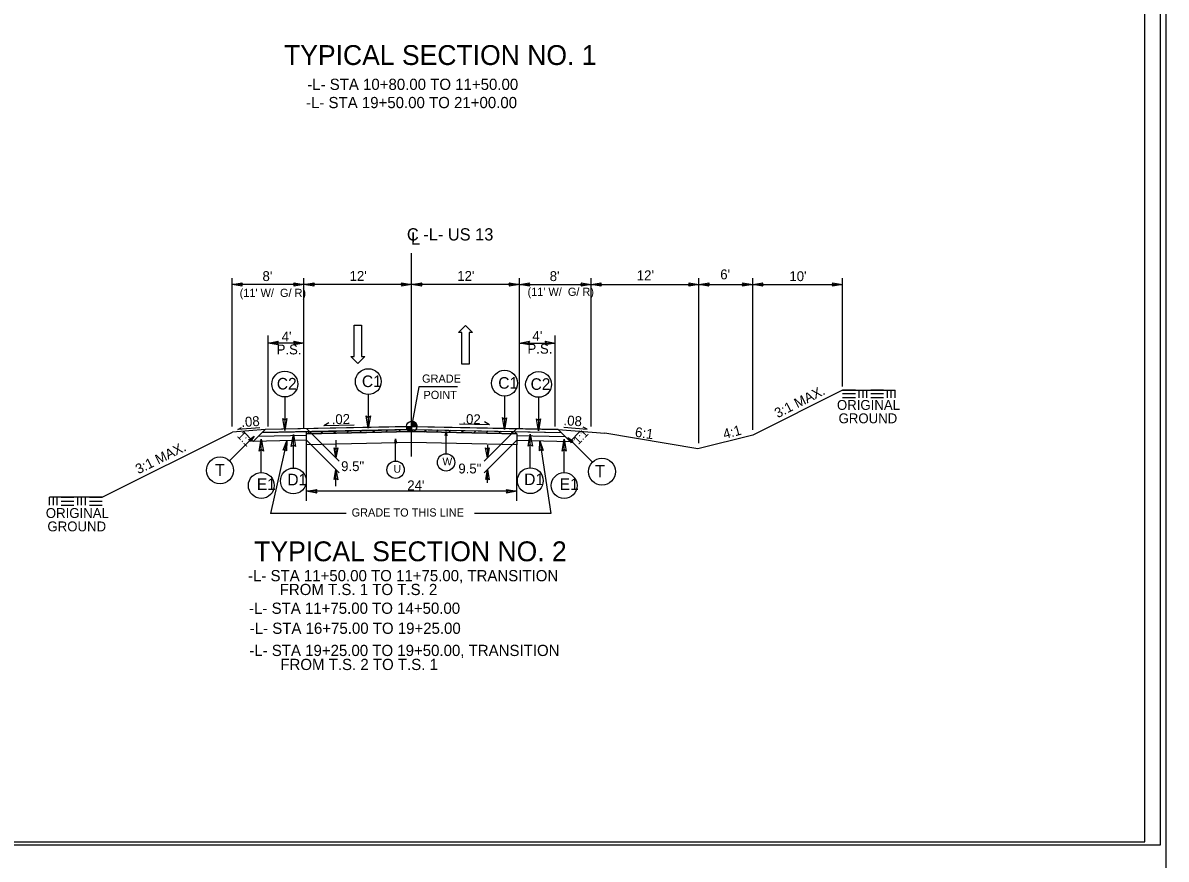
# Model space of a CAD drawing. Extents: x 9470 to 10081, y 10104 to 10463.
# Drawn here: x 9925.2 to 10052.6, y 10259.6 to 10352.7 of the extents above; entities that cross this region are included whole.
import ezdxf

# ---------------------------------------------------------------- set-up
doc = ezdxf.new("R2010")
doc.units = 0
for name, color, linetype in [('Old_Level_1', 7, 'Continuous'), ('Old_Level_11', 7, 'Continuous'), ('Old_Level_2', 7, 'Continuous'), ('Old_Level_21', 7, 'Continuous'), ('Old_Level_32', 7, 'Continuous'), ('Prop Lane Arrow CELL', 7, 'Continuous'), ('Prop Terminator CELL', 7, 'Continuous'), ('Sheet Plot Border Inside CELL', 7, 'Continuous'), ('Sheet Plot Border Outside CELL', 7, 'Continuous'), ('Sheet Typical CELL', 7, 'Continuous'), ('Typical Hinge Slope Arterial CELL', 7, 'Continuous'), ('Typical ID Circle CELL', 7, 'Continuous'), ('Typical Pavement Slope CELL', 7, 'Continuous'), ('Typical Terminator CELL', 7, 'Continuous'), ('Typical Text ID Circle CELL', 7, 'Continuous')]:
    doc.layers.add(name, color=color, linetype=linetype)

msp = doc.modelspace()

# ---------------------------------------------------------------- linework, layer by layer
at = {"layer": 'Old_Level_1'}
for p, q in [((9968.54, 10304.4), (9968.54, 10327.07)), ((9948.54, 10307.74), (9948.54, 10324.27)), ((9956.54, 10323.57), (9948.54, 10323.57)), ((9956.54, 10307.5), (9956.54, 10324.27)), ((9968.54, 10323.57), (9956.54, 10323.57)), ((9980.54, 10323.57), (9968.54, 10323.57)), ((9980.54, 10307.5), (9980.54, 10324.27)), ((9980.54, 10323.57), (9988.54, 10323.57)), ((9988.54, 10307.74), (9988.54, 10324.27)), ((9988.54, 10323.57), (10000.54, 10323.57)), ((10000.54, 10305.9), (10000.54, 10324.27)), ((10000.54, 10323.57), (10006.54, 10323.57)), ((10006.54, 10307.36), (10006.54, 10324.27)), ((10006.54, 10323.57), (10016.54, 10323.57)), ((10016.54, 10312.2), (10016.54, 10324.27)), ((9952.54, 10307.74), (9952.54, 10317.88)), ((9984.54, 10307.74), (9984.54, 10317.88)), ((9956.54, 10317.05), (9952.54, 10317.05)), ((9980.54, 10317.05), (9984.54, 10317.05)), ((10016.54, 10311.8), (10022.4, 10311.8)), ((10017.97, 10311.8), (10016.54, 10311.8)), ((10017.97, 10311.37), (10016.54, 10311.37)), ((10017.97, 10310.94), (10016.54, 10310.94)), ((10018.4, 10310.94), (10018.4, 10311.8)), ((10018.83, 10310.94), (10018.83, 10311.8)), ((10019.25, 10310.94), (10019.25, 10311.8)), ((10021.11, 10311.8), (10019.68, 10311.8)), ((10021.11, 10311.37), (10019.68, 10311.37)), ((10021.11, 10310.94), (10019.68, 10310.94)), ((10021.54, 10310.94), (10021.54, 10311.8)), ((10021.97, 10310.94), (10021.97, 10311.8)), ((10022.4, 10310.94), (10022.4, 10311.8)), ((9968.54, 10307.74), (9968.54, 10308.33)), ((9952.21, 10307.42), (9948.59, 10307.13)), ((9968.54, 10307.74), (9952.21, 10307.42)), ((9956.84, 10307.51), (9960.48, 10303.87)), ((9956.84, 10306.93), (9968.54, 10307.19)), ((9956.96, 10306.94), (9957.2, 10307.18)), ((9958.41, 10306.97), (9958.65, 10307.21)), ((9959.85, 10307), (9960.09, 10307.24)), ((9961.3, 10307.03), (9961.54, 10307.27)), ((9962.74, 10307.06), (9962.98, 10307.3)), ((9964.19, 10307.1), (9964.43, 10307.33)), ((9965.64, 10307.13), (9965.87, 10307.36)), ((9967.08, 10307.16), (9967.31, 10307.39)), ((9967.95, 10307.74), (9968.54, 10307.74)), ((9968.53, 10307.19), (9968.75, 10307.41)), ((9969.12, 10307.74), (9968.54, 10307.74)), ((9968.54, 10307.16), (9968.54, 10307.74)), ((9968.54, 10307.74), (9968.54, 10307.16)), ((9968.54, 10307.74), (9984.86, 10307.42)), ((9968.54, 10307.42), (9985.2, 10307.08)), ((9968.54, 10307.19), (9980.24, 10306.93)), ((9969.91, 10307.16), (9970.14, 10307.39)), ((9971.3, 10307.13), (9971.52, 10307.36)), ((9972.68, 10307.1), (9972.91, 10307.33)), ((9974.06, 10307.07), (9974.3, 10307.3)), ((9975.45, 10307.04), (9975.68, 10307.27)), ((9980.24, 10307.51), (9976.6, 10303.87)), ((9976.83, 10307.01), (9977.07, 10307.25)), ((9978.22, 10306.98), (9978.46, 10307.22)), ((9979.6, 10306.95), (9979.84, 10307.19)), ((9980.24, 10306.93), (9979.99, 10307.19)), ((9984.86, 10307.42), (9990.06, 10307)), ((9954.65, 10306.16), (9952.8, 10298.05)), ((9956.84, 10305.7), (9956.84, 10306.93)), ((9956.84, 10306.21), (9960.48, 10302.57)), ((9968.54, 10305.96), (9956.84, 10305.7)), ((9956.84, 10299.46), (9956.84, 10305.7)), ((9960.1, 10306.22), (9960.1, 10304.25)), ((9980.24, 10305.7), (9968.54, 10305.96)), ((9980.24, 10306.21), (9976.6, 10302.57)), ((9976.98, 10305.68), (9976.98, 10304.25)), ((9980.24, 10306.93), (9980.24, 10305.7)), ((9980.24, 10299.46), (9980.24, 10305.7)), ((9982.82, 10306.16), (9984.03, 10298.05)), ((9960.1, 10301.11), (9960.1, 10302.95)), ((9976.98, 10301.47), (9976.98, 10302.95)), ((9934.06, 10299.86), (9928.2, 10299.86)), ((9928.2, 10299), (9928.2, 10299.86)), ((9928.63, 10299), (9928.63, 10299.86)), ((9929.06, 10299), (9929.06, 10299.86)), ((9929.48, 10299.86), (9930.91, 10299.86)), ((9929.48, 10299.43), (9930.91, 10299.43)), ((9931.34, 10299), (9931.34, 10299.86)), ((9931.77, 10299), (9931.77, 10299.86)), ((9932.2, 10299), (9932.2, 10299.86)), ((9932.63, 10299.86), (9934.06, 10299.86)), ((9932.63, 10299.43), (9934.06, 10299.43)), ((9980.24, 10300.54), (9956.84, 10300.54)), ((9929.48, 10299), (9930.91, 10299)), ((9932.63, 10299), (9934.06, 10299)), ((9961.25, 10298.05), (9952.8, 10298.05)), ((9984.03, 10298.05), (9975.53, 10298.05))]:
    msp.add_line(p, q, dxfattribs=at)
for points in [[(9968.54, 10308.33), (9968.54, 10308.33), (9968.54, 10307.74)], [(9968.55, 10308.33), (9968.55, 10307.74)], [(9968.57, 10308.33), (9968.57, 10307.74)], [(9968.58, 10308.33), (9968.58, 10307.74)], [(9968.59, 10308.32), (9968.59, 10307.74)], [(9968.6, 10308.32), (9968.6, 10307.74)], [(9968.61, 10308.32), (9968.61, 10307.74)], [(9968.62, 10308.32), (9968.62, 10307.74)], [(9968.64, 10308.32), (9968.64, 10307.74)], [(9968.65, 10308.32), (9968.65, 10307.74)], [(9968.66, 10308.31), (9968.66, 10307.74)], [(9968.67, 10308.31), (9968.67, 10307.74)], [(9968.68, 10308.31), (9968.68, 10307.74)], [(9968.69, 10308.31), (9968.69, 10307.74)], [(9968.71, 10308.3), (9968.71, 10307.74)], [(9968.72, 10308.3), (9968.72, 10307.74)], [(9968.73, 10308.29), (9968.73, 10307.74)], [(9968.74, 10308.29), (9968.74, 10307.74)], [(9968.75, 10308.29), (9968.75, 10307.74)], [(9968.76, 10308.28), (9968.76, 10307.74)], [(9968.78, 10308.28), (9968.78, 10307.74)], [(9968.79, 10308.27), (9968.79, 10307.74)], [(9968.8, 10308.26), (9968.8, 10307.74)], [(9968.81, 10308.26), (9968.81, 10307.74)], [(9968.82, 10308.25), (9968.82, 10307.74)], [(9968.84, 10308.25), (9968.84, 10307.74)], [(9968.85, 10308.24), (9968.85, 10307.74)], [(9968.86, 10308.23), (9968.86, 10307.74)], [(9968.87, 10308.22), (9968.87, 10307.74)], [(9967.96, 10307.74), (9967.96, 10307.68)], [(9967.97, 10307.74), (9967.97, 10307.61)], [(9967.98, 10307.74), (9967.98, 10307.57)], [(9967.99, 10307.74), (9967.99, 10307.53)], [(9968, 10307.74), (9968, 10307.51)], [(9968.01, 10307.74), (9968.01, 10307.48)], [(9968.03, 10307.74), (9968.03, 10307.46)], [(9968.04, 10307.74), (9968.04, 10307.44)], [(9968.05, 10307.74), (9968.05, 10307.42)], [(9968.06, 10307.74), (9968.06, 10307.4)], [(9968.07, 10307.74), (9968.07, 10307.39)], [(9968.08, 10307.74), (9968.08, 10307.37)], [(9968.1, 10307.74), (9968.1, 10307.36)], [(9968.11, 10307.74), (9968.11, 10307.35)], [(9968.12, 10307.74), (9968.12, 10307.33)], [(9968.13, 10307.74), (9968.13, 10307.32)], [(9968.14, 10307.74), (9968.14, 10307.31)], [(9968.15, 10307.74), (9968.15, 10307.3)], [(9968.17, 10307.74), (9968.17, 10307.29)], [(9968.18, 10307.74), (9968.18, 10307.28)], [(9968.19, 10307.74), (9968.19, 10307.27)], [(9968.2, 10307.74), (9968.2, 10307.26)], [(9968.21, 10307.74), (9968.21, 10307.26)], [(9968.22, 10307.74), (9968.22, 10307.25)], [(9968.24, 10307.74), (9968.24, 10307.24)], [(9968.25, 10307.74), (9968.25, 10307.23)], [(9968.26, 10307.74), (9968.26, 10307.23)], [(9968.27, 10307.74), (9968.27, 10307.22)], [(9968.28, 10307.74), (9968.28, 10307.22)], [(9968.29, 10307.74), (9968.29, 10307.21)], [(9968.31, 10307.74), (9968.31, 10307.21)], [(9968.32, 10307.74), (9968.32, 10307.2)], [(9968.33, 10307.74), (9968.33, 10307.19)], [(9968.34, 10307.74), (9968.34, 10307.19)], [(9968.35, 10307.74), (9968.35, 10307.19)], [(9968.36, 10307.74), (9968.36, 10307.18)], [(9968.38, 10307.74), (9968.38, 10307.18)], [(9968.39, 10307.74), (9968.39, 10307.18)], [(9968.4, 10307.74), (9968.4, 10307.17)], [(9968.41, 10307.74), (9968.41, 10307.17)], [(9968.42, 10307.74), (9968.42, 10307.17)], [(9968.43, 10307.74), (9968.43, 10307.17)], [(9968.45, 10307.74), (9968.45, 10307.17)], [(9968.46, 10307.74), (9968.46, 10307.16)], [(9968.47, 10307.74), (9968.47, 10307.16)], [(9968.48, 10307.74), (9968.48, 10307.16)], [(9968.49, 10307.74), (9968.49, 10307.16)], [(9968.5, 10307.74), (9968.5, 10307.16)], [(9968.52, 10307.74), (9968.52, 10307.16)], [(9968.53, 10307.74), (9968.53, 10307.16), (9968.53, 10307.16)], [(9968.88, 10308.21), (9968.88, 10307.74)], [(9968.89, 10308.21), (9968.89, 10307.74)], [(9968.91, 10308.2), (9968.91, 10307.74)], [(9968.92, 10308.19), (9968.92, 10307.74)], [(9968.93, 10308.18), (9968.93, 10307.74)], [(9968.94, 10308.17), (9968.94, 10307.74)], [(9968.95, 10308.15), (9968.95, 10307.74)], [(9968.96, 10308.14), (9968.96, 10307.74)], [(9968.98, 10308.13), (9968.98, 10307.74)], [(9968.99, 10308.12), (9968.99, 10307.74)], [(9969, 10308.1), (9969, 10307.74)], [(9969.01, 10308.09), (9969.01, 10307.74)], [(9969.02, 10308.07), (9969.02, 10307.74)], [(9969.03, 10308.05), (9969.03, 10307.74)], [(9969.05, 10308.03), (9969.05, 10307.74)], [(9969.06, 10308.01), (9969.06, 10307.74)], [(9969.07, 10307.99), (9969.07, 10307.74)], [(9969.08, 10307.96), (9969.08, 10307.74)], [(9969.09, 10307.93), (9969.09, 10307.74)], [(9969.1, 10307.89), (9969.1, 10307.74)], [(9969.12, 10307.83), (9969.12, 10307.74)]]:
    msp.add_lwpolyline(points, dxfattribs=at)
msp.add_lwpolyline([(9980.24, 10306.93), (9968.54, 10307.19), (9956.84, 10306.93), (9956.84, 10307.17), (9968.54, 10307.42), (9979.99, 10307.19)], close=True, dxfattribs=at)
msp.add_circle((9968.54, 10307.74), 0.585, dxfattribs=at)
for start, end in [(359.9905, 89.9905), (179.9905, 269.9905)]:
    msp.add_arc((9968.54, 10307.74), 0.585, start, end, dxfattribs=at)
at = {"layer": 'Old_Level_11'}
for p, q in [((9969.35, 10312.17), (9968.54, 10307.74)), ((9973.65, 10312.17), (9969.35, 10312.17)), ((9949.17, 10307.4), (9949.6, 10307.62)), ((9951.62, 10307.6), (9949.17, 10307.4)), ((9985.51, 10307.66), (9988.1, 10307.45)), ((9988.1, 10307.45), (9987.66, 10307.66))]:
    msp.add_line(p, q, dxfattribs=at)
at = {"layer": 'Old_Level_2'}
for p, q in [((9977.23, 10307.93), (9976.67, 10308.27)), ((9958.76, 10307.86), (9959.32, 10308.2)), ((9958.76, 10307.86), (9962.13, 10307.93)), ((9977.23, 10307.93), (9973.86, 10308))]:
    msp.add_line(p, q, dxfattribs=at)
at = {"layer": 'Old_Level_21'}
for p, q in [((9952.21, 10307.42), (9951.88, 10307.08)), ((9951.88, 10307.08), (9968.06, 10307.41)), ((9967.95, 10307.73), (9952.21, 10307.42)), ((9984.86, 10307.42), (9969.12, 10307.73)), ((9985.2, 10307.08), (9984.86, 10307.42))]:
    msp.add_line(p, q, dxfattribs=at)
msp.add_lwpolyline([(9969.02, 10307.41), (9979.99, 10307.19), (9985.2, 10307.08)], dxfattribs=at)
for start, end in [(181.0918, 186.1998), (186.1998, 193.0547), (193.0547, 200.9216), (200.9216, 203.8341), (203.8341, 206.5155), (206.5155, 211.3101), (211.3101, 213.4322), (213.4322, 214.8222), (325.1841, 358.9134)]:
    msp.add_arc((9968.54, 10307.74), 0.585, start, end, dxfattribs=at)
at = {"layer": 'Prop Lane Arrow CELL'}
for p, q in [((9962.12, 10315.55), (9962.12, 10319.05)), ((9962.12, 10319.05), (9962.95, 10319.05)), ((9962.95, 10319.05), (9962.95, 10315.55)), ((9973.75, 10318.21), (9974.52, 10319)), ((9974.52, 10319), (9975.32, 10318.21)), ((9974.12, 10318.21), (9973.75, 10318.21)), ((9974.12, 10314.71), (9974.12, 10318.21)), ((9975.32, 10318.21), (9974.95, 10318.21)), ((9974.95, 10318.21), (9974.95, 10314.71)), ((9962.55, 10314.77), (9961.75, 10315.55)), ((9961.75, 10315.55), (9962.12, 10315.55)), ((9963.32, 10315.55), (9962.55, 10314.77)), ((9962.95, 10315.55), (9963.32, 10315.55)), ((9974.95, 10314.71), (9974.12, 10314.71))]:
    msp.add_line(p, q, dxfattribs=at)
at = {"layer": 'Prop Terminator CELL'}
for points in [[(9949.66, 10323.38), (9948.54, 10323.57), (9949.67, 10323.77), (9949.52, 10323.57)], [(9955.41, 10323.77), (9956.54, 10323.57), (9955.41, 10323.37), (9955.55, 10323.57)], [(9957.66, 10323.38), (9956.54, 10323.57), (9957.67, 10323.77), (9957.52, 10323.57)], [(9967.41, 10323.77), (9968.54, 10323.57), (9967.41, 10323.37), (9967.55, 10323.57)], [(9969.66, 10323.38), (9968.54, 10323.57), (9969.67, 10323.77), (9969.52, 10323.57)], [(9979.41, 10323.77), (9980.54, 10323.57), (9979.41, 10323.37), (9979.55, 10323.57)], [(9981.66, 10323.38), (9980.54, 10323.57), (9981.67, 10323.77), (9981.52, 10323.57)], [(9987.41, 10323.77), (9988.54, 10323.57), (9987.41, 10323.37), (9987.55, 10323.57)], [(9989.66, 10323.38), (9988.54, 10323.57), (9989.67, 10323.77), (9989.52, 10323.57)], [(9999.41, 10323.77), (10000.54, 10323.57), (9999.41, 10323.37), (9999.55, 10323.57)], [(10001.66, 10323.38), (10000.54, 10323.57), (10001.67, 10323.77), (10001.52, 10323.57)], [(10001.66, 10323.38), (10000.54, 10323.57), (10001.67, 10323.77), (10001.52, 10323.57)], [(10005.41, 10323.77), (10006.54, 10323.57), (10005.41, 10323.37), (10005.55, 10323.57)], [(10005.41, 10323.77), (10006.54, 10323.57), (10005.41, 10323.37), (10005.55, 10323.57)], [(10007.66, 10323.38), (10006.54, 10323.57), (10007.67, 10323.77), (10007.52, 10323.57)], [(10007.66, 10323.38), (10006.54, 10323.57), (10007.67, 10323.77), (10007.52, 10323.57)], [(10015.41, 10323.77), (10016.54, 10323.57), (10015.41, 10323.37), (10015.55, 10323.57)], [(9953.66, 10316.86), (9952.54, 10317.05), (9953.67, 10317.25), (9953.52, 10317.05)], [(9955.41, 10317.25), (9956.54, 10317.05), (9955.41, 10316.85), (9955.55, 10317.05)], [(9981.66, 10316.86), (9980.54, 10317.05), (9981.67, 10317.25), (9981.52, 10317.05)], [(9983.41, 10317.25), (9984.54, 10317.05), (9983.41, 10316.85), (9983.55, 10317.05)], [(9954.22, 10305.11), (9954.65, 10306.16), (9954.61, 10305.02), (9954.44, 10305.2)], [(9982.79, 10305.02), (9982.82, 10306.16), (9983.18, 10305.07), (9982.97, 10305.18)], [(9960.3, 10305.37), (9960.1, 10304.25), (9959.9, 10305.38), (9960.1, 10305.24)], [(9977.17, 10305.37), (9976.98, 10304.25), (9976.78, 10305.38), (9976.98, 10305.24)], [(9959.91, 10301.83), (9960.1, 10302.95), (9960.3, 10301.82), (9960.1, 10301.96)], [(9976.79, 10301.83), (9976.98, 10302.95), (9977.18, 10301.82), (9976.98, 10301.96)], [(9957.97, 10300.34), (9956.84, 10300.54), (9957.97, 10300.74), (9957.83, 10300.54)], [(9979.12, 10300.73), (9980.24, 10300.54), (9979.11, 10300.34), (9979.25, 10300.54)]]:
    msp.add_lwpolyline(points, close=True, dxfattribs=at)
at = {"layer": 'Sheet Plot Border Inside CELL'}
msp.add_lwpolyline([(10051.97, 10408.84), (9818.66, 10408.84), (9818.66, 10261.13), (10051.97, 10261.13)], close=True, dxfattribs=at)
at = {"layer": 'Sheet Plot Border Outside CELL'}
msp.add_lwpolyline([(10052.6, 10411.98), (9816.84, 10411.98), (9816.84, 10257.98), (10052.6, 10257.98)], close=True, dxfattribs=at)
at = {"layer": 'Sheet Typical CELL'}
msp.add_lwpolyline([(10050.22, 10408.48), (9840.22, 10408.48), (9840.22, 10261.48), (10050.22, 10261.48)], close=True, dxfattribs=at)
at = {"layer": 'Typical Hinge Slope Arterial CELL'}
for p, q in [((10016.54, 10311.8), (10006.54, 10306.8)), ((9934.06, 10299.86), (9948.59, 10307.13)), ((10000.43, 10305.27), (9990.06, 10307)), ((10006.54, 10306.8), (10000.43, 10305.27))]:
    msp.add_line(p, q, dxfattribs=at)
at = {"layer": 'Typical ID Circle CELL'}
for p, q in [((9954.41, 10311.04), (9954.41, 10307.31)), ((9963.71, 10311.31), (9963.71, 10307.58)), ((9978.89, 10311.12), (9978.89, 10307.4)), ((9982.68, 10310.99), (9982.68, 10307.27)), ((9972.37, 10304.71), (9972.37, 10307.19)), ((9948.25, 10303.92), (9950.99, 10306.67)), ((9951.79, 10302.62), (9951.79, 10306.35)), ((9955.36, 10303.12), (9955.36, 10306.85)), ((9966.75, 10303.89), (9966.75, 10306.37)), ((9981.76, 10303.16), (9981.76, 10306.88)), ((9985.53, 10302.61), (9985.53, 10306.34)), ((9988.68, 10303.78), (9985.93, 10306.53))]:
    msp.add_line(p, q, dxfattribs=at)
for centre, radius in [((9954.41, 10312.48), 1.44), ((9963.71, 10312.75), 1.44), ((9978.89, 10312.57), 1.44), ((9982.68, 10312.44), 1.44), ((9972.37, 10303.75), 0.962), ((9947.19, 10302.86), 1.5), ((9955.36, 10301.68), 1.44), ((9966.75, 10302.93), 0.962), ((9981.76, 10301.71), 1.44), ((9989.74, 10302.72), 1.5), ((9951.79, 10301.18), 1.44), ((9985.53, 10301.17), 1.44)]:
    msp.add_circle(centre, radius, dxfattribs=at)
at = {"layer": 'Typical Pavement Slope CELL'}
for p, q in [((9950.88, 10306.09), (9949.75, 10307.22)), ((9952.21, 10307.42), (9950.88, 10306.09)), ((9968.54, 10307.42), (9951.88, 10307.08)), ((9984.86, 10307.42), (9986.19, 10306.09)), ((9986.19, 10306.09), (9987.32, 10307.22)), ((9956.84, 10306.21), (9950.88, 10306.09)), ((9956.84, 10306.75), (9951.44, 10306.64)), ((9980.24, 10306.75), (9985.64, 10306.64)), ((9980.24, 10306.21), (9986.19, 10306.09))]:
    msp.add_line(p, q, dxfattribs=at)
at = {"layer": 'Typical Terminator CELL'}
for points in [[(9954.64, 10308.65), (9954.41, 10307.31), (9954.17, 10308.65), (9954.41, 10308.48)], [(9963.94, 10308.92), (9963.71, 10307.58), (9963.47, 10308.93), (9963.71, 10308.76)], [(9979.12, 10308.73), (9978.89, 10307.4), (9978.66, 10308.74), (9978.89, 10308.57)], [(9982.91, 10308.6), (9982.68, 10307.27), (9982.45, 10308.61), (9982.68, 10308.44)], [(9972.29, 10306.73), (9972.37, 10307.19), (9972.45, 10306.72), (9972.37, 10306.78)], [(9950.39, 10306.24), (9950.99, 10306.67), (9950.57, 10306.06), (9950.54, 10306.22)], [(9951.56, 10305.01), (9951.79, 10306.35), (9952.03, 10305), (9951.79, 10305.18)], [(9955.13, 10305.52), (9955.36, 10306.85), (9955.6, 10305.51), (9955.36, 10305.68)], [(9966.67, 10305.9), (9966.75, 10306.37), (9966.84, 10305.9), (9966.75, 10305.96)], [(9981.53, 10305.55), (9981.76, 10306.88), (9981.99, 10305.54), (9981.76, 10305.71)], [(9985.3, 10305), (9985.53, 10306.34), (9985.77, 10305), (9985.53, 10305.17)], [(9986.36, 10305.92), (9985.93, 10306.53), (9986.55, 10306.1), (9986.39, 10306.07)]]:
    msp.add_lwpolyline(points, close=True, dxfattribs=at)

# ---------------------------------------------------------------- texts
at = {"layer": 'Old_Level_1'}
msp.add_text('C -L- US 13', height=1.3647, dxfattribs=at).set_placement((9968.01, 10328.47))
msp.add_text('L', height=1.37, rotation=359.9469, dxfattribs=at).set_placement((9968.46, 10328.01))
at = {"layer": 'Old_Level_11'}
for s, height, p in [("8'", 1.1, (9951.92, 10323.95)), ("12'", 1.1, (9961.62, 10323.97)), ("12'", 1.1, (9973.62, 10323.97)), ("8'", 1.1, (9983.92, 10323.95)), ("12'", 1.1, (9993.62, 10324.04)), ("6'", 1.1, (10002.92, 10324.14)), ("10'", 1.1, (10010.62, 10323.94)), ("(11' W/  G/ R)", 0.91, (9949.38, 10322.18)), ("(11' W/  G/ R)", 0.91, (9981.45, 10322.3)), ("4'", 1.1, (9954.06, 10317.22)), ("4'", 1.1, (9982, 10317.3)), ('P.S.', 1.1, (9953.49, 10315.78)), ('P.S.', 1.1, (9981.44, 10315.86)), ('GRADE', 0.91, (9969.7, 10312.63)), ('POINT', 0.91, (9969.86, 10310.81)), ('9.5"', 1.1, (9960.68, 10302.78)), ("24'", 1.1, (9968.05, 10300.64)), ('GRADE TO THIS LINE ', 0.91, (9961.85, 10297.72))]:
    msp.add_text(s, height=height, dxfattribs=at).set_placement(p)
for s, height, rotation, p in [('3:1 MAX.', 1.1, 26.7764, (10009.31, 10308.66)), ('ORIGINAL', 1.1, 0.0013, (10015.92, 10309.6)), ('.08 ', 1.1, 4.0383, (9949.6, 10307.68)), ('.02', 1.1, 1.1939, (9959.64, 10308)), ('.02', 1.1, 358.8061, (9974.18, 10308.04)), ('.08 ', 1.1, 355.9617, (9985.43, 10307.91)), ('GROUND', 1.1, 0.0013, (10016.1, 10308.11)), ('1:1', 0.91, 314.0414, (9949.03, 10306.65)), ('1:1', 0.91, 46.3011, (9987.12, 10305.68)), ('6:1', 1.1, 351.993, (9993.37, 10306.61)), ('4:1', 1.1, 14.9339, (10003.39, 10306.34)), ('3:1 MAX.', 1.1, 26.3459, (9938.1, 10302.42)), ('9.5"', 1.1, 360, (9973.74, 10302.52)), ('ORIGINAL', 1.1, 359.9987, (9927.78, 10297.56)), ('GROUND', 1.1, 359.9987, (9927.96, 10296.07))]:
    msp.add_text(s, height=height, rotation=rotation, dxfattribs=at).set_placement(p)
at = {"layer": 'Old_Level_32'}
for s, height, p in [('TYPICAL SECTION NO. 1', 2.21, (9954.32, 10348.02)), ('-L- STA 10+80.00 TO 11+50.00  ', 1.25, (9956.9, 10345.24)), ('-L- STA 19+50.00 TO 21+00.00', 1.25, (9956.77, 10343.21)), ('TYPICAL SECTION NO. 2', 2.21, (9951, 10292.74)), ('-L- STA 11+50.00 TO 11+75.00, TRANSITION', 1.25, (9950.31, 10290.51)), ('FROM T.S. 1 TO T.S. 2', 1.25, (9953.84, 10288.97)), ('-L- STA 11+75.00 TO 14+50.00  ', 1.25, (9950.43, 10286.88)), ('-L- STA 16+75.00 TO 19+25.00', 1.25, (9950.5, 10284.65)), ('-L- STA 19+25.00 TO 19+50.00, TRANSITION', 1.25, (9950.45, 10282.18)), ('FROM T.S. 2 TO T.S. 1', 1.25, (9953.91, 10280.62))]:
    msp.add_text(s, height=height, dxfattribs=at).set_placement(p)
at = {"layer": 'Typical Text ID Circle CELL'}
for s, height, p in [('C1', 1.291, (9963, 10312.14)), ('C2', 1.291, (9953.52, 10311.87)), ('C1', 1.291, (9978.19, 10311.96)), ('C2', 1.291, (9981.79, 10311.83)), ('T ', 1.345, (9946.63, 10302.24)), ('U', 0.861, (9966.52, 10302.6)), ('W', 0.861, (9971.97, 10303.42)), ('T ', 1.345, (9988.97, 10302.1)), ('E1', 1.291, (9951.29, 10300.68)), ('D1', 1.291, (9954.69, 10301.19)), ('D1', 1.291, (9981.08, 10301.22)), ('E1', 1.291, (9985.03, 10300.67))]:
    msp.add_text(s, height=height, dxfattribs=at).set_placement(p)

doc.saveas('drawing.dxf')
